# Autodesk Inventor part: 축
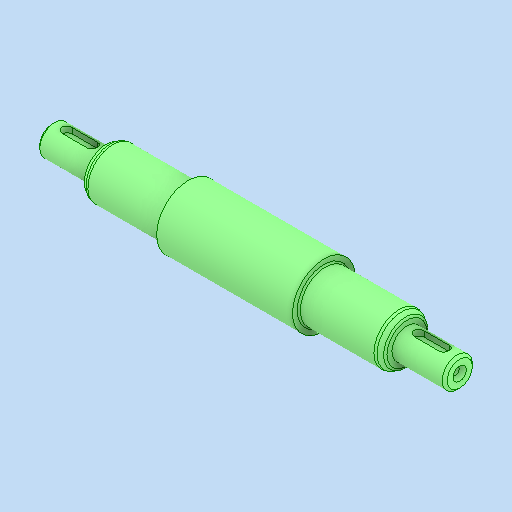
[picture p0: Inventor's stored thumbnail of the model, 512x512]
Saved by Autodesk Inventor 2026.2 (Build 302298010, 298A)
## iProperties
Created: 2026-03
Part Number: 축
Material: 강철, 탄소
Document SubType Name: Modeling
Designer: PC-2-06
Density: 7.85 g/cm^3
Appearance: 기본값
Author: jhkim
Sending System: Autodesk Inventor 2026
Preprocessor: ST-DEVELOPER v20.1
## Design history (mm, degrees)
feature "솔리드1"
node "솔리드2"
